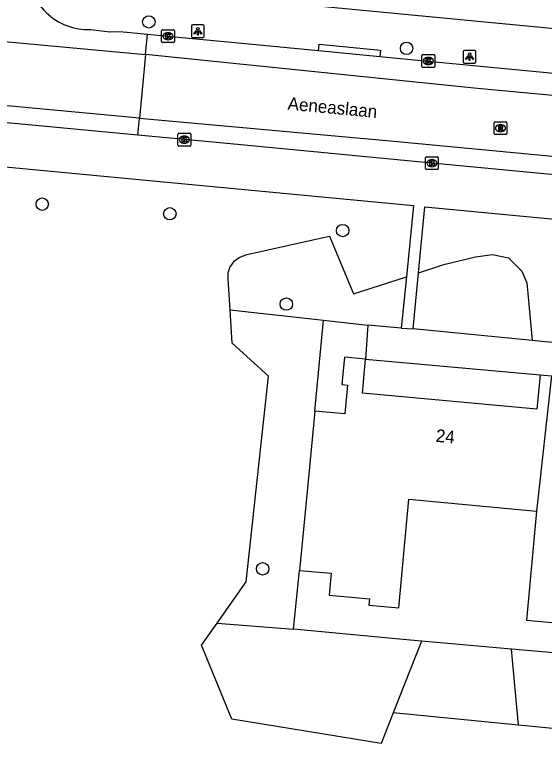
# Model space of a CAD drawing. Extents: x 162186 to 163152, y 385513 to 386513.
# Drawn here: x 162250.1 to 162291.8, y 385678.1 to 385735.4 of the extents above; entities that cross this region are included whole.
import ezdxf

# ---------------------------------------------------------------- set-up
doc = ezdxf.new("R2010")
doc.units = 0
for name, color, linetype in [('IMGEO_Boom', 7, 'Continuous'), ('IMGEO_Groenvoorziening', 7, 'Continuous'), ('IMGEO_Kolk', 7, 'Continuous'), ('IMGEO_Lichtpunt', 7, 'Continuous'), ('IMGEO_Openbare_ruimte_label', 7, 'Continuous'), ('IMGEO_Pand', 7, 'Continuous'), ('IMGEO_Pand_nummerreeks', 7, 'Continuous'), ('IMGEO_Rijbaan_lokaal_gesloten', 7, 'Continuous'), ('IMGEO_Rijbaan_lokaal_open', 7, 'Continuous'), ('IMGEO_Rioolput', 7, 'Continuous'), ('IMGEO_Voetpad_open', 7, 'Continuous')]:
    doc.layers.add(name, color=color, linetype=linetype)

msp = doc.modelspace()

# ---------------------------------------------------------------- linework, layer by layer
at = {"layer": 'IMGEO_Boom'}
for centre in [(162260.648, 385734.871), (162280.944, 385732.796), (162252.259, 385720.522), (162262.306, 385719.768), (162275.915, 385718.444), (162271.478, 385712.66), (162269.611, 385691.818)]:
    msp.add_circle(centre, 0.489, dxfattribs=at)
at = {"layer": 'IMGEO_Groenvoorziening'}
for points in [[(162267.045, 385712.214), (162266.89, 385714.61), (162266.89, 385715.131), (162267.016, 385715.55), (162267.384, 385716.071), (162267.764, 385716.338), (162268.374, 385716.568), (162274.873, 385717.999), (162276.77, 385713.467), (162280.928, 385714.816)], [(162281.877, 385715.117), (162283.808, 385715.741), (162283.992, 385715.801), (162286.365, 385716.388), (162287.711, 385716.568), (162288.981, 385716.29), (162290.011, 385715.263), (162290.418, 385714.336), (162290.575, 385712.654), (162290.842, 385709.783)], [(162266.021, 385687.549), (162268.303, 385690.787), (162270.061, 385706.994), (162267.214, 385709.594), (162267.045, 385712.214)], [(162267.045, 385712.214), (162274.392, 385711.395)], [(162273.712, 385704.24), (162274.392, 385711.395)], [(162274.392, 385711.395), (162277.907, 385711.003)], [(162272.032, 385687.08), (162272.52, 385691.7)], [(162279.896, 385680.486), (162278.945, 385678.076), (162267.173, 385679.991), (162264.792, 385685.805), (162266.021, 385687.549)], [(162266.021, 385687.549), (162272.032, 385687.08)], [(162282.125, 385686.13), (162280.396, 385686.282), (162272.032, 385687.08)], [(162282.125, 385686.13), (162279.896, 385680.486)], [(162289.198, 385685.507), (162282.125, 385686.13)], [(162289.75, 385679.525), (162289.198, 385685.507)], [(162305.235, 385684.094), (162289.198, 385685.507)], [(162289.75, 385679.525), (162279.896, 385680.486)], [(162302.141, 385678.318), (162289.75, 385679.525)]]:
    msp.add_lwpolyline(points, dxfattribs=at)
at = {"layer": 'IMGEO_Kolk'}
for p, q in [((162261.66, 385733.319), (162261.66, 385734.171)), ((162261.735, 385734.245), (162262.587, 385734.245)), ((162262.148, 385734.025), (162262.173, 385734.025)), ((162262.661, 385734.171), (162262.661, 385733.319)), ((162262.587, 385733.245), (162261.735, 385733.245)), ((162262.171, 385733.465), (162262.146, 385733.465)), ((162282.158, 385731.37), (162282.158, 385732.222)), ((162282.233, 385732.296), (162283.085, 385732.296)), ((162282.646, 385732.076), (162282.671, 385732.076)), ((162283.159, 385732.222), (162283.159, 385731.37)), ((162282.669, 385731.516), (162282.644, 385731.516)), ((162283.085, 385731.296), (162282.233, 385731.296)), ((162262.947, 385725.176), (162262.947, 385726.028)), ((162263.022, 385726.102), (162263.874, 385726.102)), ((162263.435, 385725.882), (162263.46, 385725.882)), ((162263.948, 385726.028), (162263.948, 385725.176)), ((162263.458, 385725.322), (162263.433, 385725.322)), ((162263.874, 385725.102), (162263.022, 385725.102)), ((162282.443, 385723.329), (162282.443, 385724.181)), ((162282.518, 385724.255), (162283.37, 385724.255)), ((162282.931, 385724.035), (162282.956, 385724.035)), ((162283.444, 385724.181), (162283.444, 385723.329)), ((162282.954, 385723.475), (162282.929, 385723.475)), ((162283.37, 385723.255), (162282.518, 385723.255))]:
    msp.add_line(p, q, dxfattribs=at)
for points in [[(162261.66, 385733.319), (162261.66, 385734.171)], [(162261.735, 385734.245), (162262.587, 385734.245)], [(162261.981, 385733.945), (162262.104, 385733.945), (162262.104, 385733.794), (162262.234, 385733.945), (162262.398, 385733.945), (162262.252, 385733.794), (162262.405, 385733.545), (162262.253, 385733.545), (162262.168, 385733.709), (162262.104, 385733.642), (162262.104, 385733.545), (162261.981, 385733.545), (162261.981, 385733.945)], [(162262.661, 385734.171), (162262.661, 385733.319)], [(162262.587, 385733.245), (162261.735, 385733.245)], [(162282.158, 385731.37), (162282.158, 385732.222)], [(162282.233, 385732.296), (162283.085, 385732.296)], [(162283.159, 385732.222), (162283.159, 385731.37)], [(162282.479, 385731.996), (162282.602, 385731.996), (162282.602, 385731.845), (162282.732, 385731.996), (162282.896, 385731.996), (162282.75, 385731.845), (162282.903, 385731.596), (162282.751, 385731.596), (162282.666, 385731.76), (162282.602, 385731.693), (162282.602, 385731.596), (162282.479, 385731.596), (162282.479, 385731.996)], [(162283.085, 385731.296), (162282.233, 385731.296)], [(162262.947, 385725.176), (162262.947, 385726.028)], [(162263.022, 385726.102), (162263.874, 385726.102)], [(162263.268, 385725.802), (162263.391, 385725.802), (162263.391, 385725.651), (162263.521, 385725.802), (162263.685, 385725.802), (162263.539, 385725.651), (162263.692, 385725.402), (162263.54, 385725.402), (162263.455, 385725.566), (162263.391, 385725.499), (162263.391, 385725.402), (162263.268, 385725.402), (162263.268, 385725.802)], [(162263.948, 385726.028), (162263.948, 385725.176)], [(162263.874, 385725.102), (162263.022, 385725.102)], [(162282.443, 385723.329), (162282.443, 385724.181)], [(162282.518, 385724.255), (162283.37, 385724.255)], [(162283.444, 385724.181), (162283.444, 385723.329)], [(162282.764, 385723.955), (162282.887, 385723.955), (162282.887, 385723.804), (162283.017, 385723.955), (162283.181, 385723.955), (162283.035, 385723.804), (162283.188, 385723.555), (162283.036, 385723.555), (162282.951, 385723.719), (162282.887, 385723.652), (162282.887, 385723.555), (162282.764, 385723.555), (162282.764, 385723.955)], [(162283.37, 385723.255), (162282.518, 385723.255)]]:
    msp.add_lwpolyline(points, dxfattribs=at)
for centre, start, end in [((162261.737, 385734.169), 91.55205, 178.44795), ((162261.737, 385734.169), 91.55205, 178.44795), ((162262.585, 385734.169), 1.55205, 88.44795), ((162262.585, 385734.169), 1.55205, 88.44795), ((162261.737, 385733.321), 181.55205, 268.44795), ((162261.737, 385733.321), 181.55205, 268.44795), ((162262.585, 385733.321), 271.55205, 358.44795), ((162262.585, 385733.321), 271.55205, 358.44795), ((162282.235, 385732.22), 91.55205, 178.44795), ((162282.235, 385732.22), 91.55205, 178.44795), ((162283.083, 385732.22), 1.55205, 88.44795), ((162283.083, 385732.22), 1.55205, 88.44795), ((162282.235, 385731.372), 181.55205, 268.44795), ((162282.235, 385731.372), 181.55205, 268.44795), ((162283.083, 385731.372), 271.55205, 358.44795), ((162283.083, 385731.372), 271.55205, 358.44795), ((162263.024, 385726.026), 91.55205, 178.44795), ((162263.024, 385726.026), 91.55205, 178.44795), ((162263.872, 385726.026), 1.55205, 88.44795), ((162263.872, 385726.026), 1.55205, 88.44795), ((162263.024, 385725.178), 181.55205, 268.44795), ((162263.024, 385725.178), 181.55205, 268.44795), ((162263.872, 385725.178), 271.55205, 358.44795), ((162263.872, 385725.178), 271.55205, 358.44795), ((162282.52, 385724.179), 91.55205, 178.44795), ((162282.52, 385724.179), 91.55205, 178.44795), ((162283.368, 385724.179), 1.55205, 88.44795), ((162283.368, 385724.179), 1.55205, 88.44795), ((162282.52, 385723.331), 181.55205, 268.44795), ((162282.52, 385723.331), 181.55205, 268.44795), ((162283.368, 385723.331), 271.55205, 358.44795), ((162283.368, 385723.331), 271.55205, 358.44795)]:
    msp.add_arc(centre, 0.0765, start, end, dxfattribs=at)
for centre, major_axis, ratio, start_param, end_param in [((162262.147, 385733.745), (-0.387, 0.002), 0.722429, 4.712389, 7.853982), ((162262.172, 385733.745), (-0.39, 0.002), 0.717154, 1.570796, 4.712389), ((162282.645, 385731.796), (-0.387, 0.002), 0.722429, 4.712389, 7.853982), ((162282.67, 385731.796), (-0.39, 0.002), 0.717154, 1.570796, 4.712389), ((162263.434, 385725.602), (-0.387, 0.002), 0.722429, 4.712389, 7.853982), ((162263.459, 385725.602), (-0.39, 0.002), 0.717154, 1.570796, 4.712389), ((162282.93, 385723.755), (-0.387, 0.002), 0.722429, 4.712389, 7.853982), ((162282.955, 385723.755), (-0.39, 0.002), 0.717154, 1.570796, 4.712389)]:
    msp.add_ellipse(centre, major_axis=major_axis, ratio=ratio, start_param=start_param, end_param=end_param, dxfattribs=at)
at = {"layer": 'IMGEO_Lichtpunt'}
for p, q in [((162264.012, 385734.543), (162264.012, 385733.736)), ((162264.012, 385734.543), (162264.012, 385733.736)), ((162264.914, 385734.638), (162264.106, 385734.638)), ((162264.914, 385734.638), (162264.106, 385734.638)), ((162265.008, 385733.736), (162265.008, 385734.543)), ((162265.008, 385733.736), (162265.008, 385734.543)), ((162264.106, 385733.642), (162264.914, 385733.642)), ((162264.106, 385733.642), (162264.914, 385733.642)), ((162285.408, 385732.533), (162285.408, 385731.726)), ((162285.408, 385732.533), (162285.408, 385731.726)), ((162286.31, 385732.628), (162285.502, 385732.628)), ((162286.31, 385732.628), (162285.502, 385732.628)), ((162286.404, 385731.726), (162286.404, 385732.533)), ((162286.404, 385731.726), (162286.404, 385732.533)), ((162285.502, 385731.632), (162286.31, 385731.632)), ((162285.502, 385731.632), (162286.31, 385731.632))]:
    msp.add_line(p, q, dxfattribs=at)
for points in [[(162264.386, 385734.207), (162264.425, 385734.179), (162264.237, 385733.917), (162264.199, 385733.944), (162264.386, 385734.207)], [(162264.488, 385734.159), (162264.535, 385734.159), (162264.535, 385733.837), (162264.488, 385733.837), (162264.488, 385734.159)], [(162264.598, 385734.179), (162264.636, 385734.206), (162264.823, 385733.944), (162264.784, 385733.916), (162264.598, 385734.179)], [(162285.782, 385732.197), (162285.821, 385732.169), (162285.633, 385731.907), (162285.595, 385731.934), (162285.782, 385732.197)], [(162285.884, 385732.149), (162285.931, 385732.149), (162285.931, 385731.827), (162285.884, 385731.827), (162285.884, 385732.149)], [(162285.994, 385732.169), (162286.032, 385732.196), (162286.219, 385731.934), (162286.18, 385731.906), (162285.994, 385732.169)]]:
    msp.add_lwpolyline(points, dxfattribs=at)
for centre in [(162264.511, 385734.341), (162285.907, 385732.331)]:
    msp.add_circle(centre, 0.0994, dxfattribs=at)
for centre, start, end in [((162264.106, 385734.543), 90, 180), ((162264.106, 385734.543), 90, 180), ((162264.914, 385734.543), 0, 90), ((162264.914, 385734.543), 0, 90), ((162264.106, 385733.736), 180, 270), ((162264.106, 385733.736), 180, 270), ((162264.914, 385733.736), 270, 0), ((162264.914, 385733.736), 270, 360), ((162285.502, 385732.533), 90, 180), ((162285.502, 385732.533), 90, 180), ((162286.31, 385732.533), 0, 90), ((162286.31, 385732.533), 0, 90), ((162285.502, 385731.726), 180, 270), ((162285.502, 385731.726), 180, 270), ((162286.31, 385731.726), 270, 0), ((162286.31, 385731.726), 270, 360)]:
    msp.add_arc(centre, 0.0946, start, end, dxfattribs=at)
at = {"layer": 'IMGEO_Pand'}
for points in [[(162277.711, 385708.319), (162276.046, 385708.472), (162275.848, 385706.318), (162276.298, 385706.276), (162276.091, 385704.021), (162273.712, 385704.24)], [(162291.458, 385707.094), (162291.209, 385704.381), (162277.465, 385705.645), (162277.711, 385708.319)], [(162292.352, 385707.012), (162291.172, 385696.37)], [(162291.458, 385707.094), (162292.352, 385707.012)], [(162273.712, 385704.24), (162273.239, 385699.263), (162272.52, 385691.7)], [(162272.52, 385691.7), (162275.019, 385691.47), (162274.86, 385689.747), (162278.026, 385689.455), (162277.98, 385688.957), (162280.33, 385688.741), (162281.115, 385697.294), (162291.172, 385696.37)], [(162291.172, 385696.37), (162290.382, 385687.776), (162295.779, 385687.28), (162296.563, 385695.824), (162306.491, 385694.912)]]:
    msp.add_lwpolyline(points, dxfattribs=at)
at = {"layer": 'IMGEO_Rijbaan_lokaal_gesloten'}
for points in [[(162260.556, 385733.913), (162262.149, 385733.762), (162269.071, 385733.087), (162274.014, 385732.613)], [(162448.032, 385717.26), (162447.815, 385715.531), (162435.147, 385716.798), (162424.505, 385717.305), (162408.881, 385718.15), (162367.51, 385722.111), (162286.519, 385729.622), (162260.4, 385732.301)], [(162274.014, 385732.613), (162278.838, 385732.156)], [(162278.838, 385732.156), (162282.654, 385731.794), (162294.467, 385730.661)], [(162259.786, 385725.953), (162259.916, 385727.292)], [(162259.916, 385727.292), (162279.939, 385725.485), (162345.976, 385719.242), (162380.728, 385715.866), (162402.855, 385713.753), (162412.106, 385712.917), (162421.565, 385711.819), (162434.403, 385709.622), (162446.455, 385707.767), (162446.191, 385706.141)], [(162333.913, 385718.934), (162301.454, 385721.988), (162282.94, 385723.756), (162268.178, 385725.161), (162263.448, 385725.604), (162259.786, 385725.953)]]:
    msp.add_lwpolyline(points, dxfattribs=at)
at = {"layer": 'IMGEO_Rijbaan_lokaal_open'}
for points in [[(162237.607, 385734.418), (162260.4, 385732.301)], [(162256.075, 385734.27), (162257.576, 385734.101), (162258.369, 385734.127), (162260.556, 385733.913)], [(162260.4, 385732.301), (162260.556, 385733.913)], [(162260.4, 385732.301), (162259.916, 385727.292)], [(162259.916, 385727.292), (162237.087, 385729.426)], [(162259.786, 385725.953), (162236.95, 385728.11)]]:
    msp.add_lwpolyline(points, dxfattribs=at)
msp.add_arc((162255.876, 385739.012), 4.747, 179.0032, 272.4042, dxfattribs=at)
at = {"layer": 'IMGEO_Rioolput'}
for p, q in [((162287.837, 385726.082), (162287.837, 385726.934)), ((162287.912, 385727.008), (162288.764, 385727.008)), ((162288.838, 385726.934), (162288.838, 385726.082)), ((162288.325, 385726.788), (162288.35, 385726.788)), ((162288.764, 385726.008), (162287.912, 385726.008)), ((162288.348, 385726.228), (162288.323, 385726.228))]:
    msp.add_line(p, q, dxfattribs=at)
for points in [[(162287.837, 385726.082), (162287.837, 385726.934)], [(162287.912, 385727.008), (162288.764, 385727.008)], [(162288.838, 385726.934), (162288.838, 385726.082)], [(162288.426, 385726.706), (162288.174, 385726.708), (162288.174, 385726.308)], [(162288.174, 385726.308), (162288.298, 385726.308), (162288.298, 385726.47), (162288.309, 385726.47)], [(162288.352, 385726.627), (162288.298, 385726.627), (162288.298, 385726.546)], [(162288.298, 385726.546), (162288.35, 385726.546)], [(162288.356, 385726.441), (162288.427, 385726.308), (162288.567, 385726.308), (162288.502, 385726.434)], [(162288.764, 385726.008), (162287.912, 385726.008)]]:
    msp.add_lwpolyline(points, dxfattribs=at)
for centre, radius, start, end in [((162287.914, 385726.932), 0.0765, 91.55205, 178.44795), ((162287.914, 385726.932), 0.0765, 91.55205, 178.44795), ((162288.762, 385726.932), 0.0765, 1.55205, 88.44795), ((162288.762, 385726.932), 0.0765, 1.55205, 88.44795), ((162288.308, 385726.417), 0.0533, 26.02933, 88.69889), ((162288.334, 385726.735), 0.19, 274.7715, 282.96867), ((162288.358, 385726.531), 0.0964, 77.00612, 93.18647), ((162288.372, 385726.588), 0.0378, 276.66336, 79.67722), ((162288.425, 385726.596), 0.109, 350.36119, 89.41601), ((162288.423, 385726.596), 0.112, 277.58423, 350.98172), ((162288.407, 385726.381), 0.108, 29.51342, 73.79051), ((162287.914, 385726.084), 0.0765, 181.55205, 268.44795), ((162287.914, 385726.084), 0.0765, 181.55205, 268.44795), ((162288.762, 385726.084), 0.0765, 271.55205, 358.44795), ((162288.762, 385726.084), 0.0765, 271.55205, 358.44795)]:
    msp.add_arc(centre, radius, start, end, dxfattribs=at)
for centre, major_axis, ratio, start_param, end_param in [((162288.324, 385726.508), (-0.387, 0.002), 0.722429, 4.712389, 7.853982), ((162288.349, 385726.508), (-0.39, 0.002), 0.717154, 1.570796, 4.712389)]:
    msp.add_ellipse(centre, major_axis=major_axis, ratio=ratio, start_param=start_param, end_param=end_param, dxfattribs=at)
at = {"layer": 'IMGEO_Voetpad_open'}
for points in [[(162259.069, 385737.577), (162318.739, 385731.852)], [(162274.014, 385732.613), (162274.061, 385733.11), (162278.885, 385732.653), (162278.838, 385732.156)], [(162199.552, 385728.17), (162220.237, 385726.209), (162281.48, 385720.409), (162280.928, 385714.816)], [(162281.877, 385715.117), (162282.373, 385720.324), (162296.749, 385718.963), (162295.879, 385709.284)], [(162281.457, 385710.712), (162281.877, 385715.117)], [(162280.928, 385714.816), (162280.527, 385710.753)], [(162277.907, 385711.003), (162277.711, 385708.319)], [(162280.527, 385710.753), (162277.907, 385711.003)], [(162280.527, 385710.753), (162281.457, 385710.712)], [(162290.842, 385709.783), (162281.457, 385710.712)], [(162295.879, 385709.284), (162290.842, 385709.783)], [(162277.711, 385708.319), (162291.458, 385707.094)]]:
    msp.add_lwpolyline(points, dxfattribs=at)

# ---------------------------------------------------------------- texts
at = {"layer": 'IMGEO_Openbare_ruimte_label'}
msp.add_text('Aeneaslaan', height=1, rotation=354.60854, dxfattribs=at).set_placement((162271.553, 385727.972))
at = {"layer": 'IMGEO_Pand_nummerreeks'}
msp.add_text('24', height=1, rotation=354.74544, dxfattribs=at).set_placement((162283.214, 385701.823))

doc.saveas('drawing.dxf')
